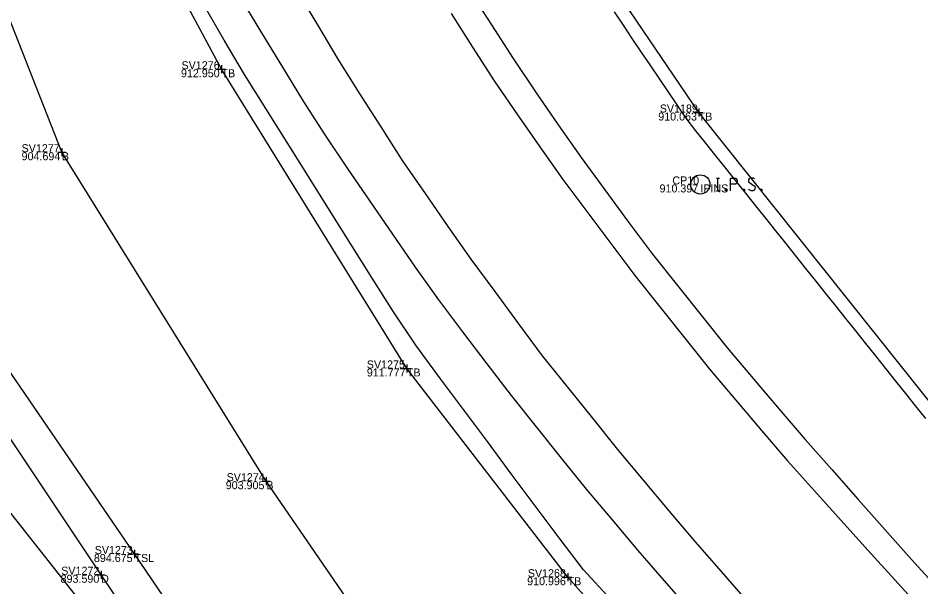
# Model space of a CAD drawing. Extents: x 1918148 to 1919797, y 624701 to 627089.
# Drawn here: x 1918934.8 to 1919047.5, y 625511 to 625582 of the extents above; entities that cross this region are included whole.
import ezdxf

# ---------------------------------------------------------------- set-up
doc = ezdxf.new("R2010")
doc.units = 0
for name, color, linetype in [('DR_X_Ditch', 7, 'Continuous'), ('PM_X_Edge_Line', 7, 'Continuous'), ('PV_X_Shoulder_Aggregate', 7, 'Continuous'), ('RD_X_Concrete_Pad', 7, 'Continuous'), ('SV_P_Mon_Cells_Set', 7, 'Continuous'), ('SV_X_Break_Lines', 7, 'Continuous'), ('SV_X_Shot_Marker', 7, 'Continuous'), ('SV_X_Text_Comment', 7, 'Continuous'), ('SV_X_Text_Elevation', 7, 'Continuous'), ('SV_X_Text_Name', 7, 'Continuous'), ('SV_X_Toe_of_Slope', 7, 'Continuous'), ('SV_X_Top_of_Bank', 7, 'Continuous')]:
    doc.layers.add(name, color=color, linetype=linetype)

msp = doc.modelspace()

# ---------------------------------------------------------------- linework, layer by layer
at = {"layer": 'DR_X_Ditch'}
msp.add_lwpolyline([(1919022.6, 625413.06), (1918990.74, 625447.13), (1918963.47, 625485.28), (1918945.14, 625512.5), (1918919.46, 625550.94), (1918912.25, 625562.33), (1918904.47, 625574.16)], dxfattribs=at)
at = {"layer": 'PM_X_Edge_Line'}
for points in [[(1918969.6, 625585.47), (1918972.15, 625581.17), (1918974.71, 625576.88), (1918977.38, 625572.65), (1918980.05, 625568.42), (1918982.74, 625564.21), (1918985.59, 625560.1), (1918988.45, 625556), (1918991.32, 625551.91), (1918994.29, 625547.88), (1918997.25, 625543.85), (1919000.23, 625539.84), (1919003.36, 625535.94), (1919006.5, 625532.05), (1919009.63, 625528.15), (1919012.84, 625524.32), (1919016.05, 625520.48), (1919019.26, 625516.65), (1919022.56, 625512.89), (1919025.85, 625509.13)], [(1918988.84, 625582.59), (1918991.53, 625578.38), (1918994.22, 625574.16), (1918997.05, 625570.04), (1918999.93, 625565.95), (1919002.81, 625561.86), (1919005.78, 625557.85), (1919008.79, 625553.85), (1919011.79, 625549.85), (1919014.9, 625545.94), (1919018.02, 625542.03), (1919021.14, 625538.12), (1919024.38, 625534.32), (1919027.62, 625530.51), (1919030.87, 625526.71), (1919034.21, 625522.99), (1919037.55, 625519.27), (1919040.89, 625515.55), (1919044.26, 625511.85), (1919047.62, 625508.15)]]:
    msp.add_lwpolyline(points, dxfattribs=at)
at = {"layer": 'PV_X_Shoulder_Aggregate'}
for points in [[(1919008.76, 625509.47), (1919005.36, 625513.13), (1919002.33, 625517.11), (1918999.35, 625521.11), (1918996.36, 625525.12), (1918993.38, 625529.13), (1918990.39, 625533.14), (1918987.41, 625537.15), (1918984.42, 625541.16), (1918981.64, 625545.31), (1918978.98, 625549.54), (1918976.33, 625553.78), (1918973.67, 625558.01), (1918971.02, 625562.24), (1918968.36, 625566.48), (1918965.7, 625570.71), (1918963.05, 625574.95), (1918960.49, 625579.24), (1918958.01, 625583.58)], [(1919009.19, 625582.78), (1919010.31, 625581.13), (1919011.43, 625579.47), (1919012.55, 625577.81), (1919013.67, 625576.16), (1919014.79, 625574.5), (1919015.91, 625572.85), (1919017.03, 625571.19), (1919018.16, 625569.53), (1919019.38, 625567.95), (1919020.63, 625566.39), (1919021.87, 625564.83), (1919023.12, 625563.26), (1919024.37, 625561.7), (1919025.61, 625560.14), (1919026.86, 625558.57), (1919028.11, 625557.01), (1919029.36, 625555.45), (1919030.6, 625553.89), (1919031.85, 625552.32), (1919033.1, 625550.76), (1919034.35, 625549.2), (1919035.59, 625547.63), (1919036.84, 625546.07), (1919038.09, 625544.51), (1919039.34, 625542.95), (1919040.58, 625541.38), (1919041.83, 625539.82), (1919043.08, 625538.26), (1919044.33, 625536.69), (1919045.57, 625535.13), (1919046.82, 625533.57), (1919048.07, 625532.01)]]:
    msp.add_lwpolyline(points, dxfattribs=at)
at = {"layer": 'RD_X_Concrete_Pad'}
for points in [[(1918991.2, 625585.38), (1918993.9, 625581.17), (1918996.59, 625576.96), (1918999.37, 625572.8), (1919002.22, 625568.7), (1919005.08, 625564.59), (1919008.02, 625560.55), (1919011.01, 625556.54), (1919014, 625552.54), (1919017.1, 625548.61), (1919020.23, 625544.71), (1919023.35, 625540.81), (1919026.58, 625536.99), (1919029.82, 625533.18), (1919033.07, 625529.38), (1919036.37, 625525.63), (1919039.68, 625521.88), (1919042.99, 625518.13), (1919046.34, 625514.42), (1919049.69, 625510.71)], [(1918962.59, 625584.44), (1918965.18, 625580.17), (1918967.78, 625575.9), (1918970.38, 625571.62), (1918973.09, 625567.42), (1918975.88, 625563.27), (1918978.69, 625559.14), (1918981.52, 625555.02), (1918984.36, 625550.9), (1918987.27, 625546.84), (1918990.28, 625542.84), (1918993.29, 625538.85), (1918996.34, 625534.89), (1918999.45, 625530.98), (1919002.57, 625527.07), (1919005.72, 625523.18), (1919008.94, 625519.36), (1919012.17, 625515.54), (1919015.43, 625511.75), (1919018.75, 625508.01)]]:
    msp.add_lwpolyline(points, dxfattribs=at)
at = {"layer": 'SV_P_Mon_Cells_Set'}
for points in [[(1919021.99, 625562.04), (1919022.34, 625562.04)], [(1919022.17, 625560.44), (1919022.17, 625562.04)], [(1919023.73, 625560.44), (1919023.73, 625562.04), (1919024.26, 625562.04), (1919024.32, 625562.03), (1919024.39, 625562), (1919024.43, 625561.98), (1919024.46, 625561.95), (1919024.51, 625561.89), (1919024.54, 625561.83), (1919024.56, 625561.72), (1919024.56, 625561.57), (1919024.55, 625561.52), (1919024.53, 625561.45), (1919024.48, 625561.36), (1919024.44, 625561.32), (1919024.41, 625561.3), (1919024.35, 625561.27), (1919024.26, 625561.26), (1919023.73, 625561.26)], [(1919026.74, 625561.93), (1919026.72, 625561.95), (1919026.69, 625561.98), (1919026.59, 625562.01), (1919026.47, 625562.04), (1919026.38, 625562.04), (1919026.35, 625562.04), (1919026.2, 625562), (1919026.08, 625561.93), (1919026, 625561.83), (1919025.98, 625561.72), (1919025.98, 625561.65), (1919026, 625561.55), (1919026.09, 625561.46), (1919026.7, 625561.08), (1919026.75, 625561.03), (1919026.78, 625560.98), (1919026.8, 625560.91), (1919026.8, 625560.83), (1919026.79, 625560.75), (1919026.78, 625560.7), (1919026.75, 625560.64), (1919026.73, 625560.59), (1919026.71, 625560.55), (1919026.68, 625560.52), (1919026.64, 625560.49), (1919026.6, 625560.46), (1919026.57, 625560.45), (1919026.47, 625560.44), (1919026.31, 625560.44), (1919026.21, 625560.46), (1919026.07, 625560.55), (1919025.98, 625560.63)], [(1919021.99, 625560.44), (1919022.34, 625560.44)], [(1919023.13, 625560.65), (1919023.18, 625560.65), (1919023.22, 625560.63), (1919023.25, 625560.58), (1919023.25, 625560.52), (1919023.22, 625560.46), (1919023.18, 625560.44), (1919023.13, 625560.44), (1919023.09, 625560.46), (1919023.06, 625560.52), (1919023.06, 625560.58), (1919023.09, 625560.63), (1919023.13, 625560.65)], [(1919025.38, 625560.65), (1919025.43, 625560.65), (1919025.46, 625560.63), (1919025.5, 625560.58), (1919025.5, 625560.52), (1919025.46, 625560.46), (1919025.43, 625560.44), (1919025.38, 625560.44), (1919025.34, 625560.46), (1919025.31, 625560.52), (1919025.31, 625560.58), (1919025.34, 625560.63), (1919025.38, 625560.65)], [(1919027.56, 625560.65), (1919027.61, 625560.65), (1919027.65, 625560.63), (1919027.68, 625560.58), (1919027.68, 625560.52), (1919027.65, 625560.46), (1919027.61, 625560.44), (1919027.56, 625560.44), (1919027.53, 625560.46), (1919027.49, 625560.52), (1919027.49, 625560.58), (1919027.53, 625560.63), (1919027.56, 625560.65)]]:
    msp.add_lwpolyline(points, dxfattribs=at)
msp.add_circle((1919019.97, 625561.24), 1.2, dxfattribs=at)
at = {"layer": 'SV_X_Break_Lines'}
msp.add_lwpolyline([(1919045.66, 625427.6), (1919011.53, 625464.07), (1918983.19, 625498.78), (1918965.77, 625524.18), (1918940.24, 625565.26), (1918931.64, 625587.04), (1918915.78, 625618.09), (1918902.81, 625643.72), (1918894.51, 625661.89), (1918884.61, 625712.49), (1918865.54, 625771.79)], dxfattribs=at)
at = {"layer": 'SV_X_Shot_Marker'}
for p, q in [((1918959.67, 625575.62), (1918960.67, 625575.62)), ((1918960.17, 625576.12), (1918960.17, 625575.12)), ((1918960.17, 625575.62), (1918960.17, 625575.62)), ((1919019.26, 625570.22), (1919020.26, 625570.22)), ((1919019.76, 625570.72), (1919019.76, 625569.72)), ((1919019.76, 625570.22), (1919019.76, 625570.22)), ((1918940.24, 625565.76), (1918940.24, 625564.76)), ((1918939.74, 625565.26), (1918940.74, 625565.26)), ((1918940.24, 625565.26), (1918940.24, 625565.26)), ((1918983.32, 625538.76), (1918983.32, 625537.76)), ((1918982.82, 625538.26), (1918983.82, 625538.26)), ((1918983.32, 625538.26), (1918983.32, 625538.26)), ((1918965.27, 625524.18), (1918966.27, 625524.18)), ((1918965.77, 625524.68), (1918965.77, 625523.68)), ((1918965.77, 625524.18), (1918965.77, 625524.18)), ((1918948.81, 625515.09), (1918949.81, 625515.09)), ((1918949.31, 625515.59), (1918949.31, 625514.59)), ((1918949.31, 625515.09), (1918949.31, 625515.09)), ((1918944.64, 625512.5), (1918945.64, 625512.5)), ((1918945.14, 625513), (1918945.14, 625512)), ((1918945.14, 625512.5), (1918945.14, 625512.5)), ((1919003.4, 625512.69), (1919003.4, 625511.69)), ((1919002.9, 625512.19), (1919003.9, 625512.19)), ((1919003.4, 625512.19), (1919003.4, 625512.19))]:
    msp.add_line(p, q, dxfattribs=at)
at = {"layer": 'SV_X_Toe_of_Slope'}
for points in [[(1919029.64, 625418.08), (1918993.83, 625449.98), (1918967.66, 625488.1), (1918949.31, 625515.09), (1918923.03, 625553.45), (1918914.75, 625563.94), (1918909.61, 625577.64)], [(1918898.69, 625570.33), (1918902.54, 625562.89), (1918917.76, 625540.86), (1918929.73, 625525.32), (1918942.08, 625509.76), (1918961.19, 625481.31), (1918987.06, 625442.58), (1919013.13, 625409.9)]]:
    msp.add_lwpolyline(points, dxfattribs=at)
at = {"layer": 'SV_X_Top_of_Bank'}
for points in [[(1919180.03, 625377.77), (1919142.39, 625420.85), (1919113.9, 625458.17), (1919086.6, 625489.42), (1919057.39, 625523.08), (1919019.76, 625570.22), (1918998.07, 625602.27), (1918985.26, 625627.56), (1918968.39, 625668.03), (1918955.62, 625707.63), (1918947.9, 625739.17), (1918945.04, 625765.59), (1918947.37, 625785.94), (1918957.93, 625802.75), (1918975.61, 625809.21), (1918997.58, 625813.39), (1919030.67, 625814.44), (1919065.45, 625812.35), (1919111.29, 625808.54)], [(1919066.32, 625440.14), (1919029.78, 625482.47), (1919003.4, 625512.19), (1918983.32, 625538.26), (1918960.17, 625575.62), (1918948.94, 625596.56), (1918932.63, 625627.72), (1918922.22, 625652.79), (1918916.09, 625672.67), (1918901.24, 625716.64), (1918882.07, 625777.61)]]:
    msp.add_lwpolyline(points, dxfattribs=at)

# ---------------------------------------------------------------- texts
at = {"layer": 'SV_X_Text_Comment'}
for s, p in [('TB', (1918960.17, 625574.62)), ('TB', (1919019.76, 625569.22)), ('B', (1918940.24, 625564.26)), ('IPINS', (1919019.97, 625560.24)), ('TB', (1918983.32, 625537.26)), ('B', (1918965.77, 625523.18)), ('TSL', (1918949.31, 625514.09)), ('D', (1918945.14, 625511.5)), ('TB', (1919003.4, 625511.19))]:
    msp.add_text(s, height=1, dxfattribs=at).set_placement(p)
at = {"layer": 'SV_X_Text_Elevation'}
for s, p in [('912.950', (1918955.11, 625574.62)), ('910.063', (1919014.71, 625569.22)), ('904.694', (1918935.21, 625564.26)), ('910.397', (1919014.87, 625560.24)), ('911.777', (1918978.32, 625537.26)), ('903.905', (1918960.7, 625523.18)), ('894.675', (1918944.24, 625514.09)), ('893.590', (1918940.08, 625511.5)), ('910.996', (1918998.34, 625511.19))]:
    msp.add_text(s, height=1, dxfattribs=at).set_placement(p)
at = {"layer": 'SV_X_Text_Name'}
for s, p in [('SV1276', (1918955.18, 625575.62)), ('SV1189', (1919014.9, 625570.22)), ('SV1277', (1918935.21, 625565.26)), ('CP10', (1919016.47, 625561.24)), ('SV1275', (1918978.32, 625538.26)), ('SV1274', (1918960.81, 625524.18)), ('SV1273', (1918944.34, 625515.09)), ('SV1272', (1918940.16, 625512.5)), ('SV1268', (1918998.42, 625512.19))]:
    msp.add_text(s, height=1, dxfattribs=at).set_placement(p)

doc.saveas('drawing.dxf')
